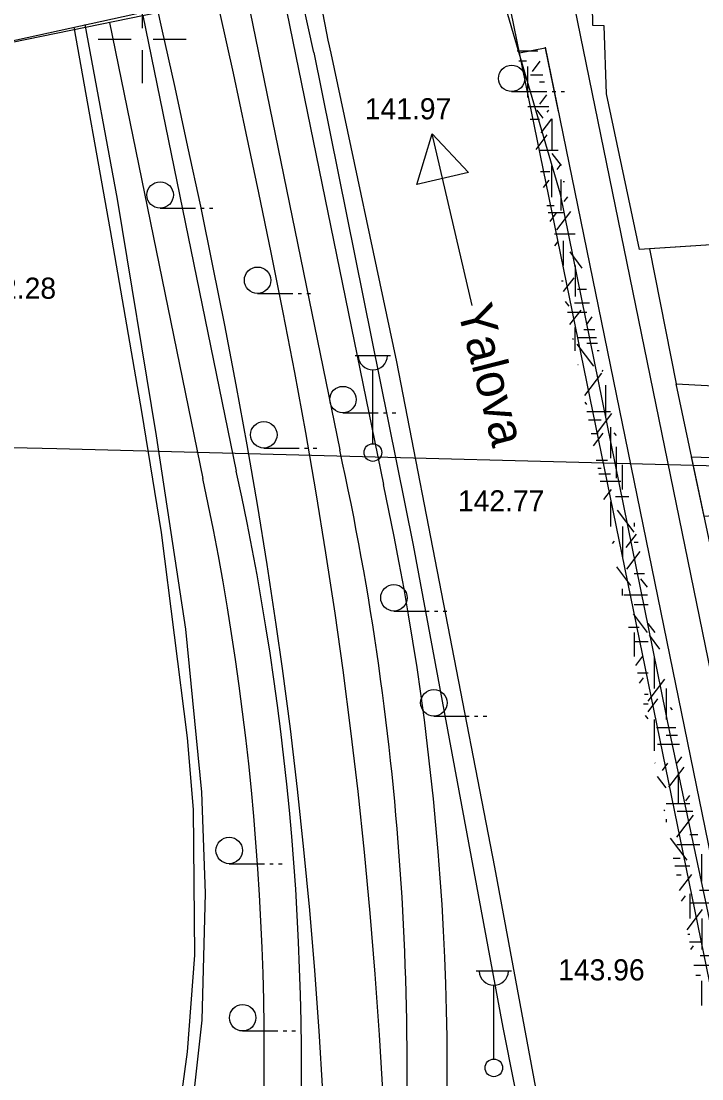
# Model space of a CAD drawing. Extents: x 419677 to 421689, y 4450851 to 4452923.
# Drawn here: x 420193.1 to 420231.8, y 4452141 to 4452201 of the extents above; entities that cross this region are included whole.
import ezdxf

# ---------------------------------------------------------------- set-up
doc = ezdxf.new("R2010")
doc.units = 0
for name, color, linetype in [('AA_HH', 7, 'Continuous'), ('Level 10', 7, 'Continuous'), ('Level 41', 7, 'Continuous'), ('Level 53', 7, 'Continuous'), ('Level 62', 7, 'Continuous'), ('Level 7', 7, 'Continuous')]:
    doc.layers.add(name, color=color, linetype=linetype)

msp = doc.modelspace()

# ---------------------------------------------------------------- linework, layer by layer
at = {"layer": 'AA_HH'}
for p, q in [((420200, 4452202.5), (420200, 4452200.625)), ((420197.5, 4452200), (420199.375, 4452200)), ((420200, 4452200), (420200, 4452200)), ((420200.625, 4452200), (420202.5, 4452200)), ((420200, 4452199.375), (420200, 4452197.5)), ((420220.97, 4452197.023), (420222.97, 4452197.023)), ((420223.27, 4452197.023), (420223.47, 4452197.023)), ((420223.77, 4452197.023), (420223.97, 4452197.023)), ((420215.589, 4452191.754), (420216.464, 4452194.626)), ((420218.721, 4452184.884), (420216.464, 4452194.626)), ((420216.464, 4452194.626), (420218.517, 4452192.432)), ((420218.517, 4452192.432), (420215.589, 4452191.754)), ((420218.469, 4452192.483), (420218.469, 4452192.483)), ((420218.469, 4452192.483), (420218.469, 4452192.483)), ((420201.019, 4452190.408), (420203.019, 4452190.408)), ((420203.319, 4452190.408), (420203.519, 4452190.408)), ((420203.819, 4452190.408), (420204.019, 4452190.408)), ((420206.55, 4452185.572), (420208.55, 4452185.572)), ((420208.85, 4452185.572), (420209.05, 4452185.572)), ((420209.35, 4452185.572), (420209.55, 4452185.572)), ((420212.094, 4452182.051), (420214.094, 4452182.051)), ((420213.094, 4452177.051), (420213.094, 4452181.244)), ((420211.395, 4452178.803), (420213.395, 4452178.803)), ((420213.695, 4452178.803), (420213.895, 4452178.803)), ((420214.195, 4452178.803), (420214.395, 4452178.803)), ((420206.904, 4452176.807), (420208.904, 4452176.807)), ((420209.204, 4452176.807), (420209.404, 4452176.807)), ((420209.704, 4452176.807), (420209.904, 4452176.807)), ((420214.286, 4452167.562), (420216.286, 4452167.562)), ((420216.586, 4452167.562), (420216.786, 4452167.562)), ((420217.086, 4452167.562), (420217.286, 4452167.562)), ((420216.554, 4452161.604), (420218.554, 4452161.604)), ((420218.854, 4452161.604), (420219.054, 4452161.604)), ((420219.354, 4452161.604), (420219.554, 4452161.604)), ((420204.94, 4452153.229), (420206.94, 4452153.229)), ((420207.24, 4452153.229), (420207.44, 4452153.229)), ((420207.74, 4452153.229), (420207.94, 4452153.229)), ((420218.957, 4452147.149), (420220.957, 4452147.149)), ((420219.957, 4452142.149), (420219.957, 4452146.342)), ((420205.703, 4452143.742), (420207.703, 4452143.742)), ((420208.003, 4452143.742), (420208.203, 4452143.742)), ((420208.503, 4452143.742), (420208.703, 4452143.742))]:
    msp.add_line(p, q, dxfattribs=at)
for points in [[(420210.807, 4452207.509), (420180.279, 4452201.103), (420180.999, 4452197.376), (420210.769, 4452203.894)], [(420420.283, 4451972.04), (420421.029, 4451970.095), (420421.342, 4451968.715), (420420.96, 4451967.485), (420420.456, 4451967.019), (420419.682, 4451966.656), (420419.467, 4451966.604), (420419.102, 4451966.589), (420380.556, 4451986.723), (420357.561, 4451999.25), (420318.688, 4452023.585), (420304.823, 4452033.943), (420285.337, 4452050.002), (420272.264, 4452064.398), (420263.435, 4452076.857), (420254.665, 4452090.863), (420245.178, 4452107.602), (420239.444, 4452119.113), (420237.151, 4452126.743), (420229.958, 4452160.587), (420223.737, 4452191.2), (420219.459, 4452205.797)], [(420209.744, 4452199.247), (420208.81, 4452203.465)], [(420210.584, 4452199.838), (420209.846, 4452203.692)], [(420194.351, 4452114.407), (420196.577, 4452118.133), (420197.638, 4452120.297), (420199.157, 4452124.192), (420200.194, 4452126.774), (420200.779, 4452128.41), (420201.324, 4452130.308), (420201.935, 4452132.88), (420202.594, 4452137.037), (420203.399, 4452144.359), (420203.587, 4452151.549), (420203.392, 4452157.288), (420202.471, 4452166.53), (420200.811, 4452177.502), (420198.603, 4452190.927), (420196.763, 4452200.827)], [(420196.116, 4452200.686), (420198.191, 4452189.146), (420199.957, 4452178.876), (420201.069, 4452172.021), (420202.558, 4452160.366), (420202.887, 4452156.311), (420202.978, 4452148.034), (420202.551, 4452142.565), (420201.94, 4452138.098)], [(420210.719, 4452199.207), (420210.58, 4452199.857)], [(420209.662, 4452098.937), (420216.106, 4452096.768), (420230.052, 4452091.143), (420230.761, 4452091.08), (420230.829, 4452091.077), (420231.145, 4452091.369), (420231.633, 4452091.722), (420231.725, 4452092.362), (420230.235, 4452099.507), (420224.819, 4452127.182), (420220.011, 4452153.036), (420214.462, 4452181.7), (420210.719, 4452199.207)], [(420209.744, 4452199.247), (420210.671, 4452194.654)], [(420210.671, 4452194.654), (420215.387, 4452171.291), (420220.477, 4452143.934), (420226.106, 4452115.606), (420229.03, 4452098.099), (420229.077, 4452097.555), (420229.076, 4452097.521), (420217.352, 4452101.902), (420209.719, 4452104.401)]]:
    msp.add_lwpolyline(points, dxfattribs=at)
for points in [[(420237.227, 4452204.473), (420235.496, 4452188.532), (420228.223, 4452188.068), (420226.352, 4452196.895), (420226.212, 4452200.745), (420225.579, 4452200.77), (420225.509, 4452205.354)], [(420254.116, 4452179.185), (420257.093, 4452193.267), (420247.74, 4452200.845), (420240.553, 4452190.955), (420239.958, 4452185.561), (420235.195, 4452186.019), (420235.496, 4452188.532), (420228.796, 4452188.104), (420230.305, 4452180.447)], [(420254.116, 4452179.185), (420251.995, 4452165.787), (420233.052, 4452167.49), (420230.305, 4452180.447)], [(420239.124, 4452179.979), (420240.033, 4452173.551), (420231.901, 4452172.92), (420231.182, 4452176.308), (420234.501, 4452176.195), (420234.775, 4452180.21)]]:
    msp.add_lwpolyline(points, close=True, dxfattribs=at)
for centre, radius in [((420220.97, 4452197.773), 0.75), ((420201.019, 4452191.158), 0.75), ((420206.55, 4452186.322), 0.75), ((420211.395, 4452179.553), 0.75), ((420206.904, 4452177.557), 0.75), ((420213.094, 4452176.551), 0.5), ((420214.286, 4452168.312), 0.75), ((420216.554, 4452162.354), 0.75), ((420204.94, 4452153.979), 0.75), ((420205.703, 4452144.492), 0.75), ((420219.957, 4452141.649), 0.5)]:
    msp.add_circle(centre, radius, dxfattribs=at)
for centre in [(420213.094, 4452182.081), (420219.957, 4452147.179)]:
    msp.add_arc(centre, 0.837, 183.298, 356.90719, dxfattribs=at)
at = {"layer": 'Level 10'}
for points in [[(420307.877, 4452088.939), (420311.575, 4452102.803), (420341.372, 4452124.392), (420225.253, 4452219.297), (420221.566, 4452216.309), (420240.697, 4452122.918), (420266.112, 4452075.76), (420281.141, 4452057.098), (420289.665, 4452048.961)], [(420172.492, 4452177.283), (420195.149, 4452176.78), (420242.848, 4452175.53), (420253.006, 4452156.4), (420287.317, 4452153.757), (420313.693, 4452131.767), (420310.654, 4452111.087), (420327.406, 4452103.4), (420329.01, 4452096.964), (420314.753, 4452088.203), (420314.554, 4452087.519)]]:
    msp.add_lwpolyline(points, dxfattribs=at)
at = {"layer": 'Level 41'}
for p, q in [((420221.273, 4452199.334), (420222.464, 4452199.334)), ((420221.381, 4452198.774), (420221.807, 4452198.774)), ((420221.882, 4452196.683), (420221.882, 4452198.451)), ((420222.146, 4452198.164), (420222.585, 4452198.741)), ((420222.036, 4452197.968), (420222.743, 4452197.968)), ((420222.553, 4452197.567), (420222.824, 4452197.567)), ((420222.572, 4452196.307), (420222.974, 4452196.836)), ((420221.883, 4452196.18), (420223.086, 4452196.18)), ((420222.759, 4452195.522), (420222.415, 4452195.974)), ((420222.985, 4452195.854), (420223.076, 4452195.974)), ((420222.023, 4452195.46), (420222.553, 4452195.46)), ((420222.652, 4452194.68), (420223.252, 4452195.47)), ((420223.252, 4452195.471), (420223.252, 4452193.74)), ((420222.358, 4452193.731), (420222.99, 4452194.564)), ((420222.553, 4452193.692), (420223.615, 4452193.692)), ((420223.79, 4452192.833), (420223.274, 4452193.512)), ((420222.599, 4452192.485), (420223.14, 4452192.485)), ((420223.225, 4452192.809), (420223.225, 4452191.042)), ((420223.558, 4452192.613), (420223.777, 4452192.9)), ((420222.774, 4452191.581), (420223.096, 4452192.005)), ((420223.757, 4452192.037), (420223.757, 4452190.269)), ((420223.896, 4452191.925), (420223.975, 4452191.925)), ((420222.972, 4452190.559), (420223.379, 4452190.559)), ((420223.957, 4452190.791), (420224.154, 4452191.05)), ((420223.05, 4452190.158), (420223.896, 4452190.158)), ((420223.147, 4452189.655), (420223.521, 4452190.147)), ((420223.532, 4452189.177), (420224.323, 4452190.219)), ((420223.395, 4452188.946), (420224.583, 4452188.946)), ((420223.414, 4452188.274), (420223.602, 4452188.521)), ((420223.896, 4452188.565), (420223.896, 4452187.167)), ((420224.977, 4452187.017), (420224.287, 4452187.925)), ((420224.568, 4452187.167), (420224.568, 4452185.4)), ((420223.918, 4452185.676), (420224.509, 4452186.453)), ((420223.8, 4452186.283), (420223.896, 4452186.283)), ((420224.699, 4452185.813), (420225.222, 4452185.813)), ((420224.224, 4452184.854), (420224.027, 4452185.114)), ((420224.28, 4452183.807), (420224.906, 4452184.631)), ((420224.539, 4452185.043), (420225.379, 4452185.043)), ((420224.142, 4452184.516), (420225.239, 4452184.516)), ((420225.209, 4452183.802), (420225.543, 4452184.241)), ((420224.568, 4452182.318), (420224.568, 4452183.633)), ((420225.073, 4452183.535), (420225.687, 4452183.535)), ((420224.442, 4452182.967), (420224.481, 4452183.018)), ((420224.699, 4452183.079), (420225.78, 4452183.079)), ((420225.239, 4452182.749), (420225.847, 4452182.749)), ((420225.635, 4452181.454), (420224.685, 4452182.703)), ((420225.818, 4452182.342), (420225.93, 4452182.342)), ((420224.719, 4452181.537), (420224.738, 4452181.537)), ((420225.129, 4452179.793), (420226.078, 4452181.043)), ((420226.101, 4452181.156), (420226.157, 4452181.23)), ((420226.3, 4452180.368), (420226.3, 4452178.601)), ((420225.236, 4452179.267), (420225.132, 4452179.403)), ((420225.239, 4452178.874), (420226.582, 4452178.874)), ((420225.849, 4452177.69), (420226.661, 4452178.76)), ((420225.326, 4452178.404), (420226.042, 4452178.404)), ((420226.582, 4452177.991), (420226.582, 4452176.224)), ((420225.475, 4452177.634), (420225.882, 4452177.634)), ((420225.613, 4452176.924), (420226.159, 4452177.643)), ((420226.916, 4452177.51), (420226.79, 4452177.676)), ((420226.9, 4452176.869), (420226.9, 4452175.101)), ((420225.767, 4452176.126), (420226.416, 4452176.126)), ((420225.855, 4452175.67), (420226.042, 4452175.67)), ((420227.254, 4452174.456), (420227.254, 4452175.854)), ((420225.919, 4452175.34), (420226.582, 4452175.34)), ((420225.998, 4452174.933), (420227.161, 4452174.933)), ((420226.202, 4452173.88), (420226.638, 4452174.453)), ((420226.582, 4452173.747), (420226.582, 4452172.349)), ((420226.857, 4452174.059), (420227.62, 4452174.059)), ((420227.926, 4452172.033), (420226.977, 4452173.282)), ((420227.925, 4452172.565), (420227.925, 4452172.349)), ((420227.925, 4452172.565), (420227.925, 4452172.349)), ((420227.254, 4452172.349), (420227.254, 4452170.582)), ((420227.254, 4452172.349), (420227.254, 4452170.582)), ((420226.686, 4452171.383), (420226.798, 4452171.531)), ((420227.474, 4452171.156), (420228.056, 4452171.923)), ((420227.925, 4452171.465), (420228.149, 4452171.465)), ((420227.5, 4452169.93), (420228.259, 4452170.928)), ((420227.739, 4452169.018), (420226.94, 4452170.069)), ((420227.925, 4452169.698), (420228.51, 4452169.698)), ((420228.67, 4452168.915), (420228.307, 4452169.392)), ((420227.254, 4452168.449), (420227.254, 4452168.815)), ((420227.336, 4452168.472), (420228.679, 4452168.472)), ((420227.925, 4452167.931), (420228.713, 4452167.931)), ((420228.684, 4452166.338), (420227.882, 4452167.394)), ((420227.602, 4452166.65), (420228.2, 4452166.65)), ((420229.107, 4452166.338), (420228.713, 4452166.856)), ((420227.925, 4452166.338), (420227.925, 4452164.984)), ((420227.925, 4452166.338), (420227.925, 4452164.984)), ((420229.387, 4452165.397), (420228.785, 4452166.19)), ((420227.925, 4452165.824), (420228.713, 4452165.824)), ((420228.024, 4452164.472), (420228.423, 4452164.997)), ((420229.075, 4452163.173), (420229.075, 4452164.94)), ((420228.105, 4452164.056), (420228.713, 4452164.056)), ((420228.219, 4452163.466), (420228.45, 4452163.77)), ((420228.723, 4452162.452), (420229.672, 4452163.701)), ((420229.746, 4452163.173), (420229.746, 4452161.406)), ((420228.509, 4452162.849), (420228.713, 4452162.849)), ((420228.713, 4452161.843), (420229.272, 4452162.579)), ((420228.447, 4452162.289), (420228.713, 4452162.289)), ((420230.091, 4452161.947), (420229.984, 4452162.088)), ((420228.713, 4452161.449), (420228.574, 4452161.631)), ((420229.075, 4452159.638), (420229.075, 4452161.406)), ((420229.198, 4452160.957), (420230.293, 4452160.957)), ((420229.252, 4452160.011), (420230.486, 4452160.011)), ((420229.746, 4452160.522), (420230.382, 4452160.522)), ((420229.107, 4452158.929), (420229.094, 4452158.945)), ((420229.523, 4452158.512), (420229.84, 4452158.929)), ((420230.36, 4452158.929), (420230.633, 4452159.289)), ((420229.734, 4452157.531), (420229.243, 4452158.177)), ((420229.894, 4452157.566), (420230.754, 4452158.698)), ((420230.414, 4452158.427), (420230.414, 4452156.66)), ((420230.854, 4452156.794), (420231.081, 4452157.093)), ((420229.746, 4452156.647), (420231.089, 4452156.647)), ((420229.621, 4452156.225), (420229.672, 4452156.292)), ((420229.746, 4452155.764), (420229.746, 4452155.581)), ((420230.348, 4452154.726), (420231.297, 4452155.976)), ((420230.37, 4452156.213), (420231.261, 4452156.213)), ((420230.933, 4452153.429), (420229.984, 4452154.679)), ((420231.089, 4452154.88), (420231.533, 4452154.88)), ((420230.343, 4452154.32), (420231.647, 4452154.32)), ((420230.14, 4452153.548), (420230.541, 4452153.548)), ((420231.761, 4452152.229), (420231.761, 4452153.761)), ((420230.224, 4452153.113), (420231.089, 4452153.113)), ((420230.323, 4452152.602), (420230.594, 4452152.602)), ((420230.498, 4452151.701), (420231.189, 4452152.611)), ((420231.622, 4452151.726), (420232.176, 4452151.726)), ((420230.613, 4452151.104), (420230.843, 4452151.407)), ((420231.089, 4452151.52), (420231.089, 4452150.122)), ((420231.089, 4452151.006), (420232.323, 4452151.006)), ((420230.927, 4452149.482), (420231.803, 4452150.635)), ((420231.761, 4452150.122), (420231.761, 4452148.355)), ((420230.975, 4452149.238), (420231.089, 4452149.238)), ((420231.059, 4452148.804), (420231.713, 4452148.804)), ((420231.144, 4452148.365), (420231.297, 4452148.567)), ((420231.676, 4452148.031), (420232.93, 4452148.031)), ((420231.317, 4452147.471), (420232.432, 4452147.471)), ((420231.425, 4452146.911), (420231.686, 4452146.911)), ((420231.761, 4452145.177), (420231.761, 4452146.588))]:
    msp.add_line(p, q, dxfattribs=at)
at = {"layer": 'Level 53'}
for points in [[(420210.26, 4452140.302), (420210.05, 4452143.742), (420209.8, 4452147.172), (420209.51, 4452150.602), (420209.18, 4452154.032), (420208.82, 4452157.462), (420208.41, 4452160.882), (420207.96, 4452164.292), (420207.61, 4452166.802), (420207.09, 4452170.202), (420206.54, 4452173.603), (420205.95, 4452176.993), (420205.33, 4452180.383), (420204.69, 4452183.773), (420204.01, 4452187.143), (420203.32, 4452190.523), (420202.6, 4452193.893), (420201.87, 4452197.253), (420201.12, 4452200.623), (420200.37, 4452203.983), (420199.6, 4452207.333), (420198.82, 4452210.693), (420197.7, 4452215.503), (420193.324, 4452234.322)], [(420205.18, 4452198.063), (420204.42, 4452201.443), (420203.66, 4452204.823), (420202.89, 4452208.203), (420202.11, 4452211.573), (420200.98, 4452216.413), (420196.825, 4452234.285)], [(420213.68, 4452140.062), (420213.47, 4452143.522), (420213.23, 4452146.972), (420212.94, 4452150.432), (420212.62, 4452153.882), (420212.25, 4452157.322), (420211.85, 4452160.762), (420211.4, 4452164.202), (420210.95, 4452167.432), (420210.43, 4452170.852), (420209.87, 4452174.273), (420209.28, 4452177.683), (420208.66, 4452181.093), (420208.01, 4452184.493), (420207.33, 4452187.893), (420206.63, 4452191.283), (420205.91, 4452194.673), (420205.18, 4452198.063)]]:
    msp.add_lwpolyline(points, dxfattribs=at)
at = {"layer": 'Level 62'}
for p, q in [((420223.885, 4452206.211), (420181.197, 4452197.477)), ((420220.131, 4452205.443), (420232.517, 4452144.902)), ((420207.92, 4452202.945), (420213.691, 4452174.738)), ((420207.92, 4452202.945), (420213.691, 4452174.738)), ((420207.92, 4452202.945), (420213.691, 4452174.738)), ((420198.147, 4452200.945), (420203.444, 4452175.085)), ((420198.147, 4452200.945), (420203.444, 4452175.085)), ((420198.147, 4452200.945), (420203.444, 4452175.085)), ((420222.866, 4452199.549), (420234.715, 4452141.643)), ((420222.879, 4452199.493), (420221.41, 4452199.193)), ((420222.879, 4452199.493), (420221.41, 4452199.193)), ((420222.879, 4452199.493), (420221.41, 4452199.193)), ((420222.879, 4452199.493), (420223.617, 4452195.886)), ((420222.879, 4452199.493), (420223.617, 4452195.886)), ((420222.879, 4452199.493), (420223.617, 4452195.886))]:
    msp.add_line(p, q, dxfattribs=at)
for centre, radius, start, end in [((420051.324, 4452142.334), 155.606, 354.57359, 12.15028), ((420060.881, 4452141.229), 156.437, 354.73542, 12.36486)]:
    msp.add_arc(centre, radius, start, end, dxfattribs=at)
at = {"layer": 'Level 7'}
for p, q in [((420205.926, 4452202.537), (420211.21, 4452176.709)), ((420200.047, 4452201.334), (420205.333, 4452175.499))]:
    msp.add_line(p, q, dxfattribs=at)
for centre, radius, start, end in [((420052.683, 4452141.669), 162.354, 354.91236, 12.46406), ((420052.683, 4452141.652), 156.357, 354.92508, 12.50177)]:
    msp.add_arc(centre, radius, start, end, dxfattribs=at)

# ---------------------------------------------------------------- texts
at = {"layer": 'AA_HH'}
for s, height, rotation, p in [('141.97 ', 1.2, 0.00255, (420212.635, 4452195.449)), ('142.28 ', 1.2, 359.99793, (420190.207, 4452185.272)), ('Yalova', 2, 284.28137, (420217.879, 4452184.692)), ('142.77 ', 1.2, 0.00255, (420217.92, 4452173.209)), ('143.96 ', 1.2, 0.00255, (420223.609, 4452146.609))]:
    msp.add_text(s, height=height, rotation=rotation, dxfattribs=at).set_placement(p)

doc.saveas('drawing.dxf')
